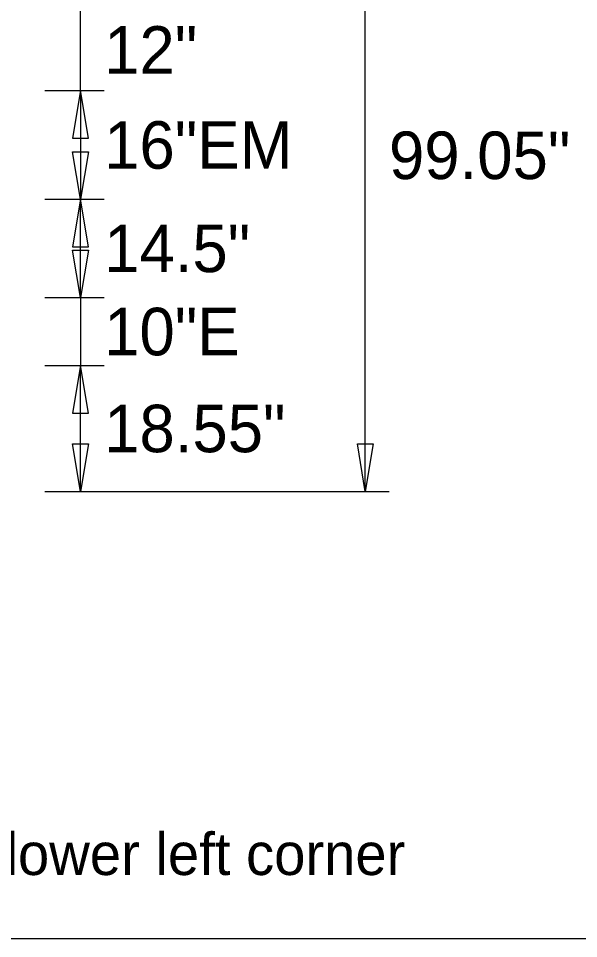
# Model space of a CAD drawing. Extents: x 2149961 to 2150220, y 145114 to 145240.
# Drawn here: x 2150047.42 to 2150054.31, y 145187.7 to 145199 of the extents above; entities that cross this region are included whole.
import ezdxf

# ---------------------------------------------------------------- set-up
doc = ezdxf.new("R2010")
doc.units = 0
doc.layers.add('GSDIMS', color=7, linetype='Continuous')
doc.layers.add('Level 1', color=7, linetype='Continuous')

msp = doc.modelspace()

# ---------------------------------------------------------------- linework, layer by layer
at = {"layer": 'GSDIMS'}
for p, q in [((2150051.687, 145193.195), (2150051.687, 145201.449)), ((2150048.187, 145198.116), (2150048.187, 145199.116)), ((2150047.749, 145198.116), (2150048.478, 145198.116)), ((2150047.749, 145198.116), (2150048.478, 145198.116)), ((2150048.187, 145198.116), (2150048.187, 145196.782)), ((2150047.749, 145196.782), (2150048.478, 145196.782)), ((2150047.749, 145196.782), (2150048.478, 145196.782)), ((2150048.187, 145195.574), (2150048.187, 145196.782)), ((2150047.749, 145195.574), (2150048.478, 145195.574)), ((2150047.749, 145195.574), (2150048.478, 145195.574)), ((2150048.187, 145195.574), (2150048.187, 145194.741)), ((2150047.749, 145194.741), (2150048.478, 145194.741)), ((2150047.749, 145194.741), (2150048.478, 145194.741)), ((2150048.187, 145193.195), (2150048.187, 145194.741)), ((2150047.749, 145193.195), (2150048.478, 145193.195)), ((2150047.749, 145193.195), (2150051.249, 145193.195)), ((2150051.249, 145193.195), (2150051.978, 145193.195))]:
    msp.add_line(p, q, dxfattribs=at)
for points in [[(2150048.187, 145198.116), (2150048.09, 145197.532), (2150048.284, 145197.532)], [(2150048.187, 145196.782), (2150048.09, 145197.366), (2150048.284, 145197.366)], [(2150048.187, 145196.782), (2150048.09, 145196.199), (2150048.284, 145196.199)], [(2150048.187, 145195.574), (2150048.09, 145196.157), (2150048.284, 145196.157)], [(2150048.187, 145194.741), (2150048.09, 145194.157), (2150048.284, 145194.157)], [(2150048.187, 145193.195), (2150048.09, 145193.778), (2150048.284, 145193.778)], [(2150051.687, 145193.195), (2150051.59, 145193.778), (2150051.784, 145193.778)]]:
    msp.add_lwpolyline(points, close=True, dxfattribs=at)
at = {"layer": 'Level 1'}
msp.add_line((2150017.557, 145187.705), (2150062.583, 145187.705), dxfattribs=at)

# ---------------------------------------------------------------- texts
at = {"layer": 'GSDIMS'}
for s, p in [('12"', (2150048.478, 145198.324)), ('16"EM', (2150048.478, 145197.157)), ('99.05"', (2150051.978, 145197.03)), ('14.5"', (2150048.478, 145195.887)), ('10"E', (2150048.478, 145194.866)), ('18.55"', (2150048.478, 145193.676))]:
    msp.add_text(s, height=0.5833, dxfattribs=at).set_placement(p)
at = {"layer": 'Level 1'}
msp.add_text('Letter locations are panel edge to lower left corner', height=0.51652, dxfattribs=at).set_placement((2150036.821, 145188.485))

doc.saveas('drawing.dxf')
